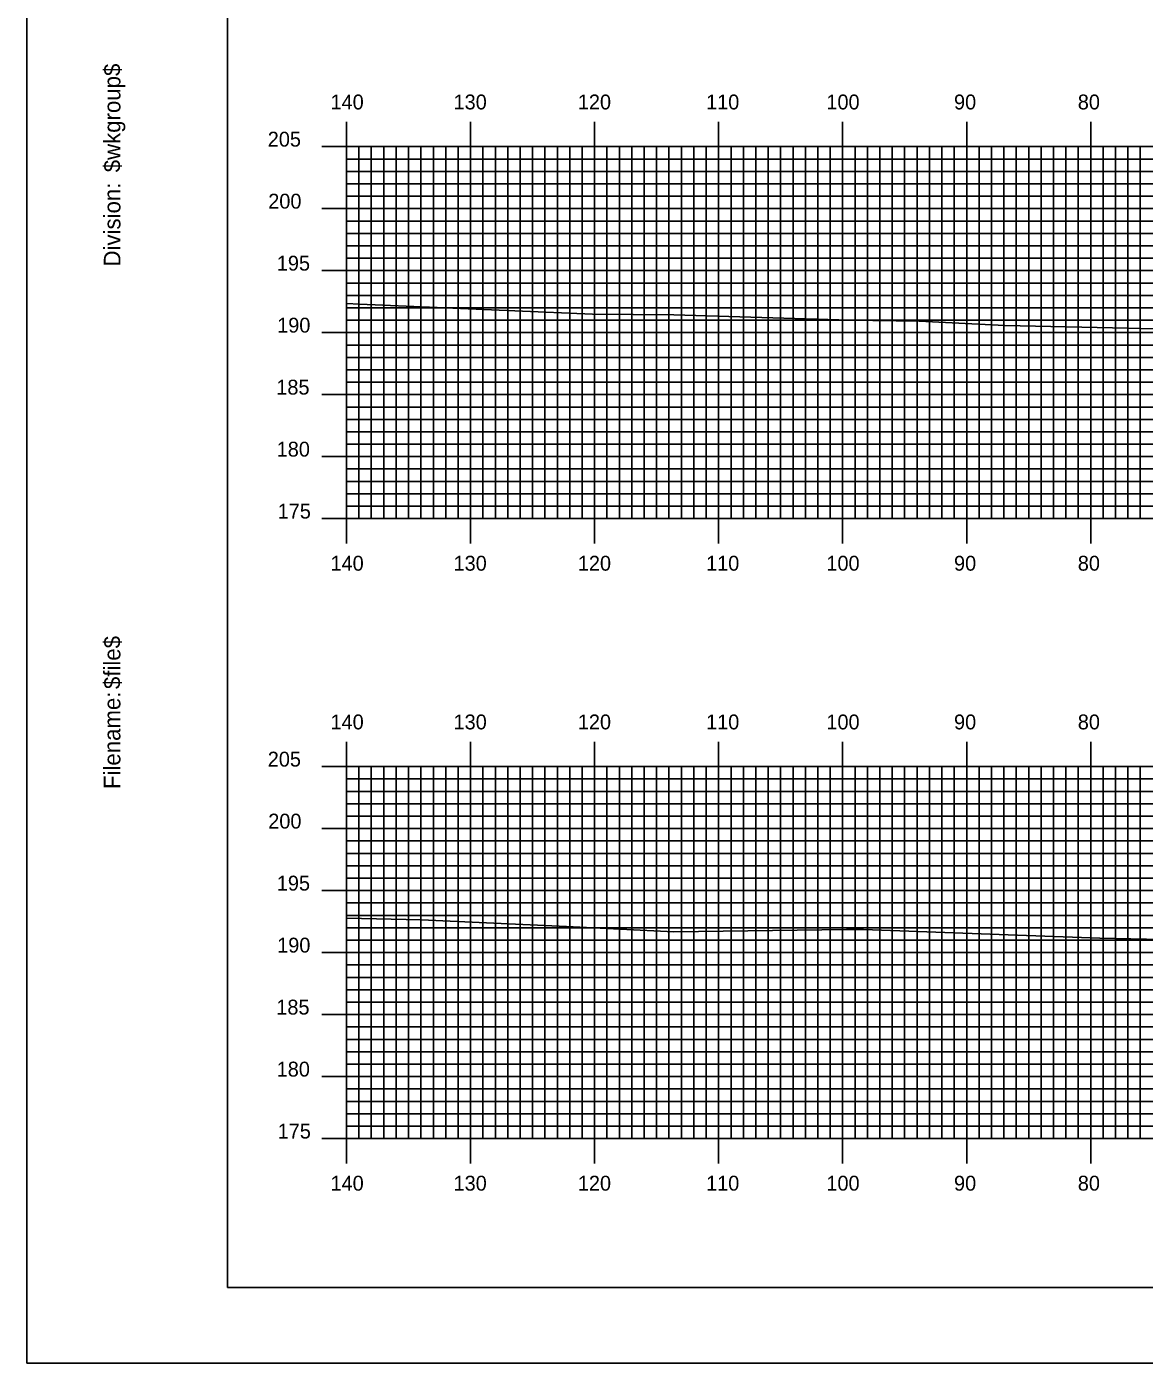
# Model space of a CAD drawing. Extents: x 1807832 to 1808175, y 442591 to 442811.
# Drawn here: x 1807832 to 1807922.1, y 442590.5 to 442698.3 of the extents above; entities that cross this region are included whole.
import ezdxf

# ---------------------------------------------------------------- set-up
doc = ezdxf.new("R2010")
doc.units = 0
for name, color, linetype in [('BORDER', 7, 'Continuous'), ('H_V ANNOTATION', 7, 'Continuous'), ('MAJOR', 7, 'Continuous'), ('MINOR', 7, 'Continuous'), ('PLOT BOUNDARY', 7, 'Continuous'), ('S_Roadway_Centerline', 7, 'Continuous')]:
    doc.layers.add(name, color=color, linetype=linetype)

msp = doc.modelspace()

# ---------------------------------------------------------------- linework, layer by layer
at = {"layer": 'BORDER'}
msp.add_lwpolyline([(1807848.18, 442596.67), (1808168.18, 442596.67), (1808168.18, 442806.67), (1807848.18, 442806.67)], close=True, dxfattribs=at)
at = {"layer": 'MAJOR'}
for p, q in [((1807857.78, 442690.67), (1807857.78, 442688.67)), ((1807867.78, 442690.67), (1807867.78, 442688.67)), ((1807877.78, 442690.67), (1807877.78, 442688.67)), ((1807887.78, 442690.67), (1807887.78, 442688.67)), ((1807897.78, 442690.67), (1807897.78, 442688.67)), ((1807907.78, 442690.67), (1807907.78, 442688.67)), ((1807917.78, 442690.67), (1807917.78, 442688.67)), ((1807855.78, 442688.67), (1807857.78, 442688.67)), ((1807857.78, 442688.67), (1808137.78, 442688.67)), ((1807857.78, 442658.67), (1807857.78, 442688.67)), ((1807857.78, 442658.67), (1807857.78, 442688.67)), ((1807857.78, 442688.67), (1808137.78, 442688.67)), ((1807867.78, 442658.67), (1807867.78, 442688.67)), ((1807877.78, 442658.67), (1807877.78, 442688.67)), ((1807887.78, 442658.67), (1807887.78, 442688.67)), ((1807897.78, 442658.67), (1807897.78, 442688.67)), ((1807907.78, 442658.67), (1807907.78, 442688.67)), ((1807917.78, 442658.67), (1807917.78, 442688.67)), ((1807855.78, 442683.67), (1807857.78, 442683.67)), ((1807857.78, 442683.67), (1808137.78, 442683.67)), ((1807855.78, 442678.67), (1807857.78, 442678.67)), ((1807857.78, 442678.67), (1808137.78, 442678.67)), ((1807855.78, 442673.67), (1807857.78, 442673.67)), ((1807857.78, 442673.67), (1808137.78, 442673.67)), ((1807855.78, 442668.67), (1807857.78, 442668.67)), ((1807857.78, 442668.67), (1808137.78, 442668.67)), ((1807855.78, 442663.67), (1807857.78, 442663.67)), ((1807857.78, 442663.67), (1808137.78, 442663.67)), ((1807855.78, 442658.67), (1807857.78, 442658.67)), ((1807857.78, 442658.67), (1808137.78, 442658.67)), ((1807857.78, 442658.67), (1808137.78, 442658.67)), ((1807857.78, 442656.66), (1807857.78, 442658.67)), ((1807867.78, 442656.66), (1807867.78, 442658.67)), ((1807877.78, 442656.66), (1807877.78, 442658.67)), ((1807887.78, 442656.66), (1807887.78, 442658.67)), ((1807897.78, 442656.66), (1807897.78, 442658.67)), ((1807907.78, 442656.66), (1807907.78, 442658.67)), ((1807917.78, 442656.66), (1807917.78, 442658.67)), ((1807857.78, 442640.67), (1807857.78, 442638.67)), ((1807867.78, 442640.67), (1807867.78, 442638.67)), ((1807877.78, 442640.67), (1807877.78, 442638.67)), ((1807887.78, 442640.67), (1807887.78, 442638.67)), ((1807897.78, 442640.67), (1807897.78, 442638.67)), ((1807907.78, 442640.67), (1807907.78, 442638.67)), ((1807917.78, 442640.67), (1807917.78, 442638.67)), ((1807855.78, 442638.67), (1807857.78, 442638.67)), ((1807857.78, 442638.67), (1808137.78, 442638.67)), ((1807857.78, 442608.67), (1807857.78, 442638.67)), ((1807857.78, 442608.67), (1807857.78, 442638.67)), ((1807857.78, 442638.67), (1808137.78, 442638.67)), ((1807867.78, 442608.67), (1807867.78, 442638.67)), ((1807877.78, 442608.67), (1807877.78, 442638.67)), ((1807887.78, 442608.67), (1807887.78, 442638.67)), ((1807897.78, 442608.67), (1807897.78, 442638.67)), ((1807907.78, 442608.67), (1807907.78, 442638.67)), ((1807917.78, 442608.67), (1807917.78, 442638.67)), ((1807855.78, 442633.67), (1807857.78, 442633.67)), ((1807857.78, 442633.67), (1808137.78, 442633.67)), ((1807855.78, 442628.67), (1807857.78, 442628.67)), ((1807857.78, 442628.67), (1808137.78, 442628.67)), ((1807855.78, 442623.67), (1807857.78, 442623.67)), ((1807857.78, 442623.67), (1808137.78, 442623.67)), ((1807855.78, 442618.67), (1807857.78, 442618.67)), ((1807857.78, 442618.67), (1808137.78, 442618.67)), ((1807855.78, 442613.67), (1807857.78, 442613.67)), ((1807857.78, 442613.67), (1808137.78, 442613.67)), ((1807855.78, 442608.67), (1807857.78, 442608.67)), ((1807857.78, 442608.67), (1808137.78, 442608.67)), ((1807857.78, 442608.67), (1808137.78, 442608.67)), ((1807857.78, 442606.66), (1807857.78, 442608.67)), ((1807867.78, 442606.66), (1807867.78, 442608.67)), ((1807877.78, 442606.66), (1807877.78, 442608.67)), ((1807887.78, 442606.66), (1807887.78, 442608.67)), ((1807897.78, 442606.66), (1807897.78, 442608.67)), ((1807907.78, 442606.66), (1807907.78, 442608.67)), ((1807917.78, 442606.66), (1807917.78, 442608.67))]:
    msp.add_line(p, q, dxfattribs=at)
at = {"layer": 'MINOR'}
for p, q in [((1807858.78, 442658.67), (1807858.78, 442688.67)), ((1807859.78, 442658.67), (1807859.78, 442688.67)), ((1807860.78, 442658.67), (1807860.78, 442688.67)), ((1807861.78, 442658.67), (1807861.78, 442688.67)), ((1807862.78, 442658.67), (1807862.78, 442688.67)), ((1807863.78, 442658.67), (1807863.78, 442688.67)), ((1807864.78, 442658.67), (1807864.78, 442688.67)), ((1807865.78, 442658.67), (1807865.78, 442688.67)), ((1807866.78, 442658.67), (1807866.78, 442688.67)), ((1807868.78, 442658.67), (1807868.78, 442688.67)), ((1807869.78, 442658.67), (1807869.78, 442688.67)), ((1807870.78, 442658.67), (1807870.78, 442688.67)), ((1807871.78, 442658.67), (1807871.78, 442688.67)), ((1807872.78, 442658.67), (1807872.78, 442688.67)), ((1807873.78, 442658.67), (1807873.78, 442688.67)), ((1807874.78, 442658.67), (1807874.78, 442688.67)), ((1807875.78, 442658.67), (1807875.78, 442688.67)), ((1807876.78, 442658.67), (1807876.78, 442688.67)), ((1807878.78, 442658.67), (1807878.78, 442688.67)), ((1807879.78, 442658.67), (1807879.78, 442688.67)), ((1807880.78, 442658.67), (1807880.78, 442688.67)), ((1807881.78, 442658.67), (1807881.78, 442688.67)), ((1807882.78, 442658.67), (1807882.78, 442688.67)), ((1807883.78, 442658.67), (1807883.78, 442688.67)), ((1807884.78, 442658.67), (1807884.78, 442688.67)), ((1807885.78, 442658.67), (1807885.78, 442688.67)), ((1807886.78, 442658.67), (1807886.78, 442688.67)), ((1807888.78, 442658.67), (1807888.78, 442688.67)), ((1807889.78, 442658.67), (1807889.78, 442688.67)), ((1807890.78, 442658.67), (1807890.78, 442688.67)), ((1807891.78, 442658.67), (1807891.78, 442688.67)), ((1807892.78, 442658.67), (1807892.78, 442688.67)), ((1807893.78, 442658.67), (1807893.78, 442688.67)), ((1807894.78, 442658.67), (1807894.78, 442688.67)), ((1807895.78, 442658.67), (1807895.78, 442688.67)), ((1807896.78, 442658.67), (1807896.78, 442688.67)), ((1807898.78, 442658.67), (1807898.78, 442688.67)), ((1807899.78, 442658.67), (1807899.78, 442688.67)), ((1807900.78, 442658.67), (1807900.78, 442688.67)), ((1807901.78, 442658.67), (1807901.78, 442688.67)), ((1807902.78, 442658.67), (1807902.78, 442688.67)), ((1807903.78, 442658.67), (1807903.78, 442688.67)), ((1807904.78, 442658.67), (1807904.78, 442688.67)), ((1807905.78, 442658.67), (1807905.78, 442688.67)), ((1807906.78, 442658.67), (1807906.78, 442688.67)), ((1807908.78, 442658.67), (1807908.78, 442688.67)), ((1807909.78, 442658.67), (1807909.78, 442688.67)), ((1807910.78, 442658.67), (1807910.78, 442688.67)), ((1807911.78, 442658.67), (1807911.78, 442688.67)), ((1807912.78, 442658.67), (1807912.78, 442688.67)), ((1807913.78, 442658.67), (1807913.78, 442688.67)), ((1807914.78, 442658.67), (1807914.78, 442688.67)), ((1807915.78, 442658.67), (1807915.78, 442688.67)), ((1807916.78, 442658.67), (1807916.78, 442688.67)), ((1807918.78, 442658.67), (1807918.78, 442688.67)), ((1807919.78, 442658.67), (1807919.78, 442688.67)), ((1807920.78, 442658.67), (1807920.78, 442688.67)), ((1807921.78, 442658.67), (1807921.78, 442688.67)), ((1807857.78, 442687.67), (1808137.78, 442687.67)), ((1807857.78, 442687.67), (1807859.79, 442687.67)), ((1807857.78, 442686.67), (1808137.78, 442686.67)), ((1807857.78, 442686.67), (1807859.79, 442686.67)), ((1807857.78, 442685.67), (1808137.78, 442685.67)), ((1807857.78, 442685.67), (1807859.79, 442685.67)), ((1807857.78, 442684.67), (1808137.78, 442684.67)), ((1807857.78, 442684.67), (1807859.79, 442684.67)), ((1807857.78, 442682.67), (1808137.78, 442682.67)), ((1807857.78, 442682.67), (1807859.79, 442682.67)), ((1807857.78, 442681.67), (1808137.78, 442681.67)), ((1807857.78, 442681.67), (1807859.79, 442681.67)), ((1807857.78, 442680.67), (1808137.78, 442680.67)), ((1807857.78, 442680.67), (1807859.79, 442680.67)), ((1807857.78, 442679.67), (1808137.78, 442679.67)), ((1807857.78, 442679.67), (1807859.79, 442679.67)), ((1807857.78, 442677.67), (1808137.78, 442677.67)), ((1807857.78, 442677.67), (1807859.79, 442677.67)), ((1807857.78, 442676.67), (1808137.78, 442676.67)), ((1807857.78, 442676.67), (1807859.79, 442676.67)), ((1807857.78, 442675.67), (1808137.78, 442675.67)), ((1807857.78, 442675.67), (1807859.79, 442675.67)), ((1807857.78, 442674.67), (1808137.78, 442674.67)), ((1807857.78, 442674.67), (1807859.79, 442674.67)), ((1807857.78, 442672.67), (1808137.78, 442672.67)), ((1807857.78, 442672.67), (1807859.79, 442672.67)), ((1807857.78, 442671.67), (1808137.78, 442671.67)), ((1807857.78, 442671.67), (1807859.79, 442671.67)), ((1807857.78, 442670.67), (1808137.78, 442670.67)), ((1807857.78, 442670.67), (1807859.79, 442670.67)), ((1807857.78, 442669.67), (1808137.78, 442669.67)), ((1807857.78, 442669.67), (1807859.79, 442669.67)), ((1807857.78, 442667.67), (1808137.78, 442667.67)), ((1807857.78, 442667.67), (1807859.79, 442667.67)), ((1807857.78, 442666.67), (1808137.78, 442666.67)), ((1807857.78, 442666.67), (1807859.79, 442666.67)), ((1807857.78, 442665.67), (1808137.78, 442665.67)), ((1807857.78, 442665.67), (1807859.79, 442665.67)), ((1807857.78, 442664.67), (1808137.78, 442664.67)), ((1807857.78, 442664.67), (1807859.79, 442664.67)), ((1807857.78, 442662.67), (1808137.78, 442662.67)), ((1807857.78, 442662.67), (1807859.79, 442662.67)), ((1807857.78, 442661.67), (1808137.78, 442661.67)), ((1807857.78, 442661.67), (1807859.79, 442661.67)), ((1807857.78, 442660.67), (1808137.78, 442660.67)), ((1807857.78, 442660.67), (1807859.79, 442660.67)), ((1807857.78, 442659.67), (1808137.78, 442659.67)), ((1807857.78, 442659.67), (1807859.79, 442659.67)), ((1807858.78, 442608.67), (1807858.78, 442638.67)), ((1807859.78, 442608.67), (1807859.78, 442638.67)), ((1807860.78, 442608.67), (1807860.78, 442638.67)), ((1807861.78, 442608.67), (1807861.78, 442638.67)), ((1807862.78, 442608.67), (1807862.78, 442638.67)), ((1807863.78, 442608.67), (1807863.78, 442638.67)), ((1807864.78, 442608.67), (1807864.78, 442638.67)), ((1807865.78, 442608.67), (1807865.78, 442638.67)), ((1807866.78, 442608.67), (1807866.78, 442638.67)), ((1807868.78, 442608.67), (1807868.78, 442638.67)), ((1807869.78, 442608.67), (1807869.78, 442638.67)), ((1807870.78, 442608.67), (1807870.78, 442638.67)), ((1807871.78, 442608.67), (1807871.78, 442638.67)), ((1807872.78, 442608.67), (1807872.78, 442638.67)), ((1807873.78, 442608.67), (1807873.78, 442638.67)), ((1807874.78, 442608.67), (1807874.78, 442638.67)), ((1807875.78, 442608.67), (1807875.78, 442638.67)), ((1807876.78, 442608.67), (1807876.78, 442638.67)), ((1807878.78, 442608.67), (1807878.78, 442638.67)), ((1807879.78, 442608.67), (1807879.78, 442638.67)), ((1807880.78, 442608.67), (1807880.78, 442638.67)), ((1807881.78, 442608.67), (1807881.78, 442638.67)), ((1807882.78, 442608.67), (1807882.78, 442638.67)), ((1807883.78, 442608.67), (1807883.78, 442638.67)), ((1807884.78, 442608.67), (1807884.78, 442638.67)), ((1807885.78, 442608.67), (1807885.78, 442638.67)), ((1807886.78, 442608.67), (1807886.78, 442638.67)), ((1807888.78, 442608.67), (1807888.78, 442638.67)), ((1807889.78, 442608.67), (1807889.78, 442638.67)), ((1807890.78, 442608.67), (1807890.78, 442638.67)), ((1807891.78, 442608.67), (1807891.78, 442638.67)), ((1807892.78, 442608.67), (1807892.78, 442638.67)), ((1807893.78, 442608.67), (1807893.78, 442638.67)), ((1807894.78, 442608.67), (1807894.78, 442638.67)), ((1807895.78, 442608.67), (1807895.78, 442638.67)), ((1807896.78, 442608.67), (1807896.78, 442638.67)), ((1807898.78, 442608.67), (1807898.78, 442638.67)), ((1807899.78, 442608.67), (1807899.78, 442638.67)), ((1807900.78, 442608.67), (1807900.78, 442638.67)), ((1807901.78, 442608.67), (1807901.78, 442638.67)), ((1807902.78, 442608.67), (1807902.78, 442638.67)), ((1807903.78, 442608.67), (1807903.78, 442638.67)), ((1807904.78, 442608.67), (1807904.78, 442638.67)), ((1807905.78, 442608.67), (1807905.78, 442638.67)), ((1807906.78, 442608.67), (1807906.78, 442638.67)), ((1807908.78, 442608.67), (1807908.78, 442638.67)), ((1807909.78, 442608.67), (1807909.78, 442638.67)), ((1807910.78, 442608.67), (1807910.78, 442638.67)), ((1807911.78, 442608.67), (1807911.78, 442638.67)), ((1807912.78, 442608.67), (1807912.78, 442638.67)), ((1807913.78, 442608.67), (1807913.78, 442638.67)), ((1807914.78, 442608.67), (1807914.78, 442638.67)), ((1807915.78, 442608.67), (1807915.78, 442638.67)), ((1807916.78, 442608.67), (1807916.78, 442638.67)), ((1807918.78, 442608.67), (1807918.78, 442638.67)), ((1807919.78, 442608.67), (1807919.78, 442638.67)), ((1807920.78, 442608.67), (1807920.78, 442638.67)), ((1807921.78, 442608.67), (1807921.78, 442638.67)), ((1807857.78, 442637.67), (1808137.78, 442637.67)), ((1807857.78, 442637.67), (1807859.79, 442637.67)), ((1807857.78, 442636.67), (1808137.78, 442636.67)), ((1807857.78, 442636.67), (1807859.79, 442636.67)), ((1807857.78, 442635.67), (1808137.78, 442635.67)), ((1807857.78, 442635.67), (1807859.79, 442635.67)), ((1807857.78, 442634.67), (1808137.78, 442634.67)), ((1807857.78, 442634.67), (1807859.79, 442634.67)), ((1807857.78, 442632.67), (1808137.78, 442632.67)), ((1807857.78, 442632.67), (1807859.79, 442632.67)), ((1807857.78, 442631.67), (1808137.78, 442631.67)), ((1807857.78, 442631.67), (1807859.79, 442631.67)), ((1807857.78, 442630.67), (1808137.78, 442630.67)), ((1807857.78, 442630.67), (1807859.79, 442630.67)), ((1807857.78, 442629.67), (1808137.78, 442629.67)), ((1807857.78, 442629.67), (1807859.79, 442629.67)), ((1807857.78, 442627.67), (1808137.78, 442627.67)), ((1807857.78, 442627.67), (1807859.79, 442627.67)), ((1807857.78, 442626.67), (1808137.78, 442626.67)), ((1807857.78, 442626.67), (1807859.79, 442626.67)), ((1807857.78, 442625.67), (1808137.78, 442625.67)), ((1807857.78, 442625.67), (1807859.79, 442625.67)), ((1807857.78, 442624.67), (1808137.78, 442624.67)), ((1807857.78, 442624.67), (1807859.79, 442624.67)), ((1807857.78, 442622.67), (1808137.78, 442622.67)), ((1807857.78, 442622.67), (1807859.79, 442622.67)), ((1807857.78, 442621.67), (1808137.78, 442621.67)), ((1807857.78, 442621.67), (1807859.79, 442621.67)), ((1807857.78, 442620.67), (1808137.78, 442620.67)), ((1807857.78, 442620.67), (1807859.79, 442620.67)), ((1807857.78, 442619.67), (1808137.78, 442619.67)), ((1807857.78, 442619.67), (1807859.79, 442619.67)), ((1807857.78, 442617.67), (1808137.78, 442617.67)), ((1807857.78, 442617.67), (1807859.79, 442617.67)), ((1807857.78, 442616.67), (1808137.78, 442616.67)), ((1807857.78, 442616.67), (1807859.79, 442616.67)), ((1807857.78, 442615.67), (1808137.78, 442615.67)), ((1807857.78, 442615.67), (1807859.79, 442615.67)), ((1807857.78, 442614.67), (1808137.78, 442614.67)), ((1807857.78, 442614.67), (1807859.79, 442614.67)), ((1807857.78, 442612.67), (1808137.78, 442612.67)), ((1807857.78, 442612.67), (1807859.79, 442612.67)), ((1807857.78, 442611.67), (1808137.78, 442611.67)), ((1807857.78, 442611.67), (1807859.79, 442611.67)), ((1807857.78, 442610.67), (1808137.78, 442610.67)), ((1807857.78, 442610.67), (1807859.79, 442610.67)), ((1807857.78, 442609.67), (1808137.78, 442609.67)), ((1807857.78, 442609.67), (1807859.79, 442609.67))]:
    msp.add_line(p, q, dxfattribs=at)
at = {"layer": 'PLOT BOUNDARY'}
msp.add_lwpolyline([(1807832, 442590.55), (1808172, 442590.55), (1808172, 442810.55), (1807832, 442810.55)], close=True, dxfattribs=at)
at = {"layer": 'S_Roadway_Centerline'}
for points in [[(1807857.78, 442676.03), (1807858.84, 442675.96), (1807877.6, 442675.16), (1807884.17, 442675.09), (1807898.37, 442674.67), (1807903.95, 442674.58), (1807910.85, 442674.24), (1807920.78, 442674.04), (1807927.94, 442673.83)], [(1807857.78, 442626.44), (1807863.81, 442626.32), (1807875.51, 442625.78), (1807884.16, 442625.34), (1807898.1, 442625.54), (1807899.47, 442625.53), (1807910.4, 442625.12), (1807918.52, 442624.84), (1807928.55, 442624.62)]]:
    msp.add_lwpolyline(points, dxfattribs=at)

# ---------------------------------------------------------------- texts
at = {"layer": 'BORDER'}
for s, p in [('$wkgroup$', (1807839.55, 442686.6)), ('Division:', (1807839.55, 442679)), ('$file$', (1807839.55, 442644.92)), ('Filename:', (1807839.55, 442636.86))]:
    msp.add_text(s, height=1.339, rotation=90, dxfattribs=at).set_placement(p)
at = {"layer": 'H_V ANNOTATION'}
for s, p in [('140', (1807856.49, 442691.67)), ('130', (1807866.41, 442691.67)), ('120', (1807876.43, 442691.67)), ('110', (1807886.77, 442691.67)), ('100', (1807896.47, 442691.67)), ('90', (1807906.76, 442691.67)), ('80', (1807916.74, 442691.67)), ('205', (1807851.43, 442688.67)), ('200', (1807851.47, 442683.67)), ('195', (1807852.16, 442678.67)), ('190', (1807852.19, 442673.67)), ('185', (1807852.12, 442668.67)), ('180', (1807852.15, 442663.67)), ('175', (1807852.23, 442658.67)), ('140', (1807856.49, 442654.47)), ('130', (1807866.41, 442654.47)), ('120', (1807876.43, 442654.47)), ('110', (1807886.77, 442654.47)), ('100', (1807896.47, 442654.47)), ('90', (1807906.76, 442654.47)), ('80', (1807916.74, 442654.47)), ('140', (1807856.49, 442641.67)), ('130', (1807866.41, 442641.67)), ('120', (1807876.43, 442641.67)), ('110', (1807886.77, 442641.67)), ('100', (1807896.47, 442641.67)), ('90', (1807906.76, 442641.67)), ('80', (1807916.74, 442641.67)), ('205', (1807851.43, 442638.67)), ('200', (1807851.47, 442633.67)), ('195', (1807852.16, 442628.67)), ('190', (1807852.19, 442623.67)), ('185', (1807852.12, 442618.67)), ('180', (1807852.15, 442613.67)), ('175', (1807852.23, 442608.67)), ('140', (1807856.49, 442604.47)), ('130', (1807866.41, 442604.47)), ('120', (1807876.43, 442604.47)), ('110', (1807886.77, 442604.47)), ('100', (1807896.47, 442604.47)), ('90', (1807906.76, 442604.47)), ('80', (1807916.74, 442604.47))]:
    msp.add_text(s, height=1.2, dxfattribs=at).set_placement(p)
at = {"layer": 'MAJOR'}
for p in [(1807857.78, 442658.67), (1807857.78, 442608.67)]:
    msp.add_text('-', height=0.012, dxfattribs=at).set_placement(p)

doc.saveas('drawing.dxf')
